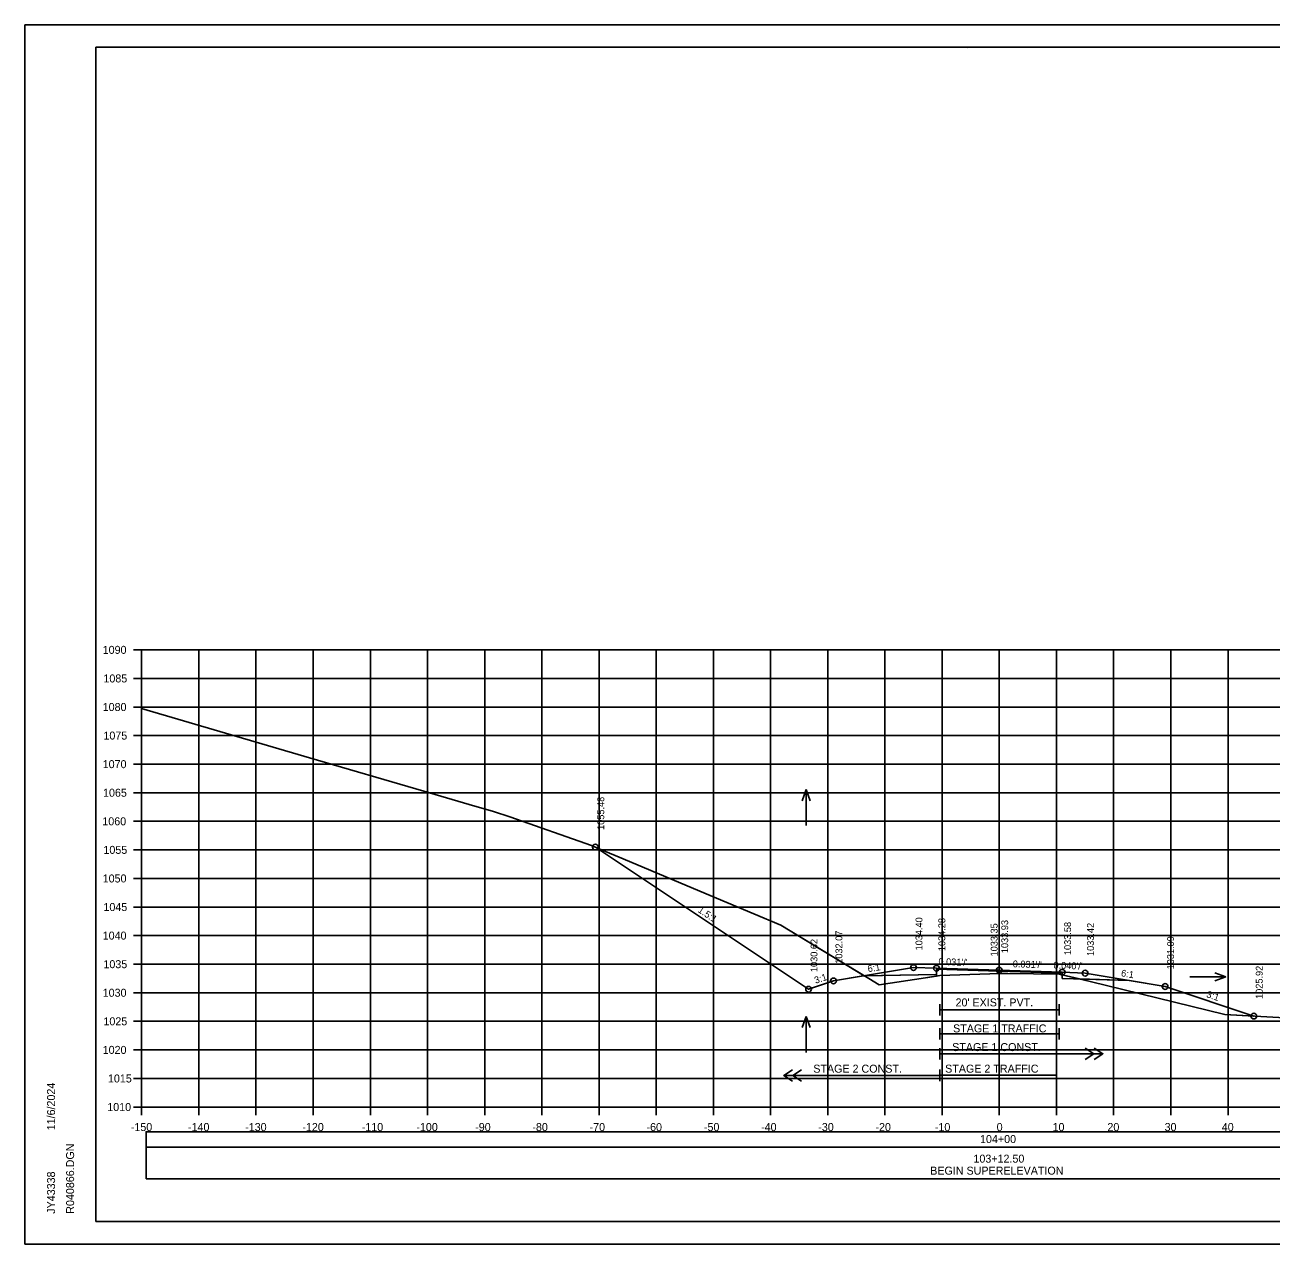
# Model space of a CAD drawing. Extents: x 1370565 to 1374448, y 301010 to 304637.
# Drawn here: x 1370564.6 to 1370782.6, y 301437.2 to 301650.5 of the extents above; entities that cross this region are included whole.
import ezdxf

# ---------------------------------------------------------------- set-up
doc = ezdxf.new("R2010")
doc.units = 0
for name, color, linetype in [('R_Alt Surface', 7, 'Continuous'), ('R_Axis', 7, 'Continuous'), ('R_Axis Annot', 7, 'Continuous'), ('R_Border', 7, 'Continuous'), ('R_Contours', 7, 'Continuous'), ('R_Drive', 7, 'Continuous'), ('R_Exist Surface', 7, 'Continuous'), ('R_Fin Surface', 7, 'Continuous'), ('R_Grid', 7, 'Continuous'), ('R_No Plot', 7, 'Continuous'), ('R_Water', 7, 'Continuous'), ('R_Water Annot', 7, 'Continuous'), ('R_Xsect Elev', 7, 'Continuous'), ('R_Xsect Slope', 7, 'Continuous')]:
    doc.layers.add(name, color=color, linetype=linetype)

msp = doc.modelspace()

# ---------------------------------------------------------------- linework, layer by layer
at = {"layer": 'R_Alt Surface'}
for points in [[(1370711.24, 301484.09), (1370724.03, 301484.35), (1370724.02, 301484.35), (1370724.03, 301485.26), (1370735.03, 301484.92), (1370746.03, 301484.57), (1370746.04, 301483.65), (1370746.03, 301483.65), (1370757.79, 301483.28)], [(1370724.65, 301479.15), (1370724.65, 301477.15)], [(1370745.49, 301479.15), (1370745.49, 301477.15)], [(1370724.65, 301478.15), (1370745.49, 301478.15)], [(1370724.65, 301474.94), (1370724.65, 301472.94)], [(1370745.49, 301474.94), (1370745.49, 301472.94)], [(1370724.65, 301473.94), (1370745.49, 301473.94)], [(1370724.65, 301471.47), (1370724.65, 301469.47)], [(1370724.65, 301470.47), (1370753.14, 301470.47)], [(1370750.04, 301471.47), (1370751.54, 301470.47), (1370750.04, 301469.47)], [(1370751.64, 301471.47), (1370753.14, 301470.47), (1370751.64, 301469.47)], [(1370698.84, 301467.68), (1370697.34, 301466.68), (1370698.84, 301465.68)], [(1370697.34, 301466.68), (1370724.65, 301466.68)], [(1370700.44, 301467.68), (1370698.94, 301466.68), (1370700.44, 301465.68)], [(1370724.65, 301467.7), (1370724.65, 301465.7)], [(1370724.65, 301466.7), (1370745.03, 301466.7)], [(1370745.03, 301467.7), (1370745.03, 301465.7)]]:
    msp.add_lwpolyline(points, dxfattribs=at)
at = {"layer": 'R_Axis'}
for p, q in [((1370583.63, 301541.15), (1370585.03, 301541.15)), ((1370585.03, 301461.15), (1370585.03, 301541.15)), ((1370583.63, 301536.15), (1370585.03, 301536.15)), ((1370583.63, 301531.15), (1370585.03, 301531.15)), ((1370583.63, 301526.15), (1370585.03, 301526.15)), ((1370583.63, 301521.15), (1370585.03, 301521.15)), ((1370583.63, 301516.15), (1370585.03, 301516.15)), ((1370583.63, 301511.15), (1370585.03, 301511.15)), ((1370583.63, 301506.15), (1370585.03, 301506.15)), ((1370583.63, 301501.15), (1370585.03, 301501.15)), ((1370583.63, 301496.15), (1370585.03, 301496.15)), ((1370583.63, 301491.15), (1370585.03, 301491.15)), ((1370583.63, 301486.15), (1370585.03, 301486.15)), ((1370583.63, 301481.15), (1370585.03, 301481.15)), ((1370583.63, 301476.15), (1370585.03, 301476.15)), ((1370583.63, 301471.15), (1370585.03, 301471.15)), ((1370583.63, 301466.15), (1370585.03, 301466.15)), ((1370583.63, 301461.15), (1370585.03, 301461.15)), ((1370585.03, 301461.15), (1370885.03, 301461.15)), ((1370585.03, 301459.75), (1370585.03, 301461.15)), ((1370595.03, 301459.75), (1370595.03, 301461.15)), ((1370605.03, 301459.75), (1370605.03, 301461.15)), ((1370615.03, 301459.75), (1370615.03, 301461.15)), ((1370625.03, 301459.75), (1370625.03, 301461.15)), ((1370635.03, 301459.75), (1370635.03, 301461.15)), ((1370645.03, 301459.75), (1370645.03, 301461.15)), ((1370655.03, 301459.75), (1370655.03, 301461.15)), ((1370665.03, 301459.75), (1370665.03, 301461.15)), ((1370675.03, 301459.75), (1370675.03, 301461.15)), ((1370685.03, 301459.75), (1370685.03, 301461.15)), ((1370695.03, 301459.75), (1370695.03, 301461.15)), ((1370705.03, 301459.75), (1370705.03, 301461.15)), ((1370715.03, 301459.75), (1370715.03, 301461.15)), ((1370725.03, 301459.75), (1370725.03, 301461.15)), ((1370735.03, 301459.75), (1370735.03, 301461.15)), ((1370745.03, 301459.75), (1370745.03, 301461.15)), ((1370755.03, 301459.75), (1370755.03, 301461.15)), ((1370765.03, 301459.75), (1370765.03, 301461.15)), ((1370775.03, 301459.75), (1370775.03, 301461.15))]:
    msp.add_line(p, q, dxfattribs=at)
for points in [[(1370724.65, 301479.15), (1370724.65, 301477.15)], [(1370745.49, 301479.15), (1370745.49, 301477.15)], [(1370724.65, 301478.15), (1370745.49, 301478.15)], [(1370724.65, 301474.94), (1370724.65, 301472.94)], [(1370745.49, 301474.94), (1370745.49, 301472.94)], [(1370724.65, 301473.94), (1370745.49, 301473.94)]]:
    msp.add_lwpolyline(points, dxfattribs=at)
at = {"layer": 'R_Border'}
for p, q in [((1370577.03, 301646.61), (1370893.21, 301646.61)), ((1370577.03, 301441.15), (1370577.03, 301646.61)), ((1370729.55, 301646.35), (1370729.55, 301646.35)), ((1370729.55, 301646.35), (1370729.55, 301646.35)), ((1370577.03, 301441.15), (1370577.03, 301441.15)), ((1370893.21, 301441.15), (1370577.03, 301441.15))]:
    msp.add_line(p, q, dxfattribs=at)
at = {"layer": 'R_Contours'}
for p, q in [((1370724.03, 301484.35), (1370711.47, 301484.09)), ((1370711.47, 301484.09), (1370712.23, 301483.63)), ((1370724.03, 301484.35), (1370724.03, 301484.05)), ((1370724.03, 301484.05), (1370724.03, 301484.35)), ((1370724.03, 301484.35), (1370724.03, 301484.05)), ((1370734.95, 301484.92), (1370734.95, 301484.5)), ((1370749.06, 301483.56), (1370746.03, 301484.29)), ((1370746.03, 301484.29), (1370746.04, 301483.65)), ((1370746.04, 301483.65), (1370749.06, 301483.56)), ((1370757.79, 301483.28), (1370749.06, 301483.56)), ((1370749.06, 301483.56), (1370750.95, 301483.1))]:
    msp.add_line(p, q, dxfattribs=at)
for points in [[(1370711.42, 301484.12), (1370696.82, 301492.95), (1370682.65, 301498.92), (1370669.22, 301504.57), (1370665.48, 301506.17), (1370664.38, 301506.64)], [(1370664.38, 301506.64), (1370701.67, 301481.77), (1370706.03, 301483.22), (1370711.24, 301484.09), (1370711.42, 301484.12)], [(1370712.23, 301483.63), (1370714.02, 301482.53), (1370722.1, 301483.75), (1370724.03, 301484.05)], [(1370734.95, 301484.92), (1370724.03, 301485.26), (1370724.03, 301484.35)], [(1370724.03, 301484.05), (1370724.65, 301484.15), (1370733.39, 301484.44), (1370734.95, 301484.5)], [(1370734.95, 301484.5), (1370734.95, 301484.92), (1370734.95, 301484.92)], [(1370735.03, 301484.92), (1370734.95, 301484.92)], [(1370734.95, 301484.5), (1370736.52, 301484.49), (1370745.49, 301484.42), (1370746.03, 301484.29)], [(1370746.03, 301484.29), (1370746.03, 301484.57), (1370735.03, 301484.92)], [(1370750.95, 301483.1), (1370774.5, 301477.35), (1370779.54, 301477.07)], [(1370779.54, 301477.07), (1370764.03, 301482.24), (1370757.79, 301483.28)]]:
    msp.add_lwpolyline(points, dxfattribs=at)
at = {"layer": 'R_Drive'}
for points in [[(1370585.82, 301454.14), (1370884.24, 301454.14), (1370884.24, 301456.84), (1370585.82, 301456.84)], [(1370585.82, 301448.61), (1370884.24, 301448.61), (1370884.24, 301454.14), (1370585.82, 301454.14)]]:
    msp.add_lwpolyline(points, close=True, dxfattribs=at)
at = {"layer": 'R_Exist Surface'}
msp.add_lwpolyline([(1370585.03, 301530.88), (1370614.38, 301522.28), (1370634.38, 301516.42), (1370642.31, 301514.1), (1370646.57, 301512.85), (1370649.44, 301511.92), (1370663.72, 301506.91), (1370665.48, 301506.17), (1370669.22, 301504.57), (1370682.65, 301498.92), (1370696.82, 301492.95), (1370712.23, 301483.63), (1370714.02, 301482.53), (1370722.1, 301483.75), (1370724.65, 301484.15), (1370733.39, 301484.44), (1370734.95, 301484.5), (1370736.52, 301484.49), (1370745.49, 301484.42), (1370750.95, 301483.1), (1370774.5, 301477.35), (1370814.43, 301475.14)], dxfattribs=at)
at = {"layer": 'R_Fin Surface'}
msp.add_lwpolyline([(1370664.38, 301506.64), (1370701.67, 301481.77), (1370706.03, 301483.22), (1370720.03, 301485.55), (1370724.03, 301485.43), (1370735.03, 301485.08), (1370746.03, 301484.74), (1370750.03, 301484.58), (1370764.03, 301482.24), (1370779.54, 301477.07)], dxfattribs=at)
at = {"layer": 'R_Grid'}
for p, q in [((1370585.03, 301541.15), (1370885.03, 301541.15)), ((1370585.03, 301461.15), (1370585.03, 301541.15)), ((1370595.03, 301461.15), (1370595.03, 301541.15)), ((1370605.03, 301461.15), (1370605.03, 301541.15)), ((1370615.03, 301461.15), (1370615.03, 301541.15)), ((1370625.03, 301461.15), (1370625.03, 301541.15)), ((1370635.03, 301461.15), (1370635.03, 301541.15)), ((1370645.03, 301461.15), (1370645.03, 301541.15)), ((1370655.03, 301461.15), (1370655.03, 301541.15)), ((1370665.03, 301461.15), (1370665.03, 301541.15)), ((1370675.03, 301461.15), (1370675.03, 301541.15)), ((1370685.03, 301461.15), (1370685.03, 301541.15)), ((1370695.03, 301461.15), (1370695.03, 301541.15)), ((1370705.03, 301461.15), (1370705.03, 301541.15)), ((1370715.03, 301461.15), (1370715.03, 301541.15)), ((1370725.03, 301461.15), (1370725.03, 301541.15)), ((1370735.03, 301461.15), (1370735.03, 301541.15)), ((1370745.03, 301461.15), (1370745.03, 301541.15)), ((1370755.03, 301461.15), (1370755.03, 301541.15)), ((1370765.03, 301461.15), (1370765.03, 301541.15)), ((1370775.03, 301461.15), (1370775.03, 301541.15)), ((1370585.03, 301536.15), (1370885.03, 301536.15)), ((1370585.03, 301531.15), (1370885.03, 301531.15)), ((1370585.03, 301526.15), (1370885.03, 301526.15)), ((1370585.03, 301521.15), (1370885.03, 301521.15)), ((1370585.03, 301516.15), (1370885.03, 301516.15)), ((1370585.03, 301511.15), (1370885.03, 301511.15)), ((1370585.03, 301506.15), (1370885.03, 301506.15)), ((1370585.03, 301501.15), (1370885.03, 301501.15)), ((1370585.03, 301496.15), (1370885.03, 301496.15)), ((1370585.03, 301491.15), (1370885.03, 301491.15)), ((1370585.03, 301486.15), (1370885.03, 301486.15)), ((1370585.03, 301481.15), (1370885.03, 301481.15)), ((1370585.03, 301476.15), (1370885.03, 301476.15)), ((1370585.03, 301471.15), (1370885.03, 301471.15)), ((1370585.03, 301466.15), (1370885.03, 301466.15)), ((1370585.03, 301461.15), (1370885.03, 301461.15))]:
    msp.add_line(p, q, dxfattribs=at)
at = {"layer": 'R_No Plot'}
for p, q in [((1370564.63, 301650.51), (1370897.96, 301650.51)), ((1370564.63, 301437.17), (1370897.96, 301437.17))]:
    msp.add_line(p, q, dxfattribs=at)
for points in [[(1370564.62, 301650.51), (1370897.96, 301650.51), (1370897.96, 301437.17), (1370564.62, 301437.17)], [(1370810.95, 301646.61), (1370830.57, 301646.61), (1370830.57, 301636.73), (1370846.68, 301636.73), (1370869.88, 301636.73), (1370869.88, 301604.06), (1370893.09, 301604.06), (1370893.21, 301441.15), (1370577.03, 301441.15), (1370577.03, 301646.61)]]:
    msp.add_lwpolyline(points, close=True, dxfattribs=at)
for centre in [(1370664.38, 301506.64), (1370720.03, 301485.55), (1370724.03, 301485.43), (1370735.03, 301485.08), (1370706.03, 301483.22), (1370746.03, 301484.74), (1370750.03, 301484.58), (1370701.67, 301481.77), (1370764.03, 301482.24), (1370779.54, 301477.07)]:
    msp.add_circle(centre, 0.5, dxfattribs=at)
at = {"layer": 'R_Water Annot'}
for p, q in [((1370701.24, 301516.69), (1370700.54, 301514.76)), ((1370701.24, 301510.4), (1370701.24, 301516.69)), ((1370701.24, 301516.69), (1370701.94, 301514.76)), ((1370768.36, 301483.92), (1370774.64, 301483.92)), ((1370774.64, 301483.92), (1370772.72, 301484.62)), ((1370774.64, 301483.92), (1370772.72, 301483.22)), ((1370701.24, 301477), (1370700.54, 301475.07)), ((1370701.24, 301470.71), (1370701.24, 301477)), ((1370701.24, 301477), (1370701.94, 301475.07))]:
    msp.add_line(p, q, dxfattribs=at)
at = {"layer": 'R_Xsect Elev'}
msp.add_line((1370735.03, 301484.5), (1370735.03, 301494.5), dxfattribs=at)

# ---------------------------------------------------------------- texts
at = {"layer": 'R_Axis Annot'}
for s, p in [('1090', (1370578.22, 301540.45)), ('1085', (1370578.35, 301535.45)), ('1080', (1370578.22, 301530.45)), ('1075', (1370578.35, 301525.45)), ('1070', (1370578.22, 301520.45)), ('1065', (1370578.28, 301515.45)), ('1060', (1370578.16, 301510.45)), ('1055', (1370578.35, 301505.45)), ('1050', (1370578.22, 301500.45)), ('1045', (1370578.35, 301495.45)), ('1040', (1370578.22, 301490.45)), ('1035', (1370578.35, 301485.45)), ('1030', (1370578.22, 301480.45)), ("20' EXIST. PVT.", (1370727.38, 301478.76)), ('1025', (1370578.35, 301475.45)), ('1020', (1370578.22, 301470.45)), ('1015', (1370579.14, 301465.45)), ('1010', (1370579.02, 301460.45)), ('-150', (1370583.14, 301456.95)), ('-140', (1370593.14, 301456.95)), ('-130', (1370603.14, 301456.95)), ('-120', (1370613.14, 301456.95)), ('-110', (1370623.53, 301456.95)), ('-100', (1370633.08, 301456.95)), ('-90', (1370643.37, 301456.95)), ('-80', (1370653.37, 301456.95)), ('-70', (1370663.37, 301456.95)), ('-60', (1370673.33, 301456.95)), ('-50', (1370683.37, 301456.95)), ('-40', (1370693.37, 301456.95)), ('-30', (1370703.37, 301456.95)), ('-20', (1370713.37, 301456.95)), ('-10', (1370723.76, 301456.95)), ('0', (1370734.57, 301456.95)), ('10', (1370744.34, 301456.95)), ('20', (1370753.94, 301456.95)), ('30', (1370763.94, 301456.95)), ('40', (1370773.94, 301456.95)), ('104+00', (1370731.66, 301454.85)), ('BEGIN SUPERELEVATION', (1370722.95, 301449.32)), ('103+12.50', (1370730.51, 301451.42))]:
    msp.add_text(s, height=1.4, dxfattribs=at).set_placement(p)
at = {"layer": 'R_Border'}
for s, p in [('11/6/2024', (1370569.89, 301457.08)), ('R040866.DGN', (1370573.22, 301442.48)), ('JY43338', (1370569.89, 301442.48))]:
    msp.add_text(s, height=1.4, rotation=90, dxfattribs=at).set_placement(p)
at = {"layer": 'R_Water'}
for s, p in [('STAGE 1 TRAFFIC', (1370726.95, 301474.21)), ('STAGE 1 CONST.', (1370726.79, 301470.94)), ('STAGE 2 CONST.', (1370702.5, 301467.16)), ('STAGE 2 TRAFFIC', (1370725.56, 301467.17))]:
    msp.add_text(s, height=1.4, dxfattribs=at).set_placement(p)
at = {"layer": 'R_Xsect Elev'}
for s, p in [('1055.48', (1370665.93, 301509.64)), ('1034.40', (1370721.58, 301488.55)), ('1034.28', (1370725.58, 301488.43)), ('1033.35', (1370734.73, 301487.5)), ('1033.93', (1370736.58, 301488.08)), ('1033.58', (1370747.58, 301487.74)), ('1033.42', (1370751.58, 301487.58)), ('1030.62', (1370703.22, 301484.77)), ('1032.07', (1370707.58, 301486.22)), ('1031.09', (1370765.58, 301485.24)), ('1025.92', (1370781.09, 301480.07))]:
    msp.add_text(s, height=1.2, rotation=90, dxfattribs=at).set_placement(p)
at = {"layer": 'R_Xsect Slope'}
for s, rotation, p in [('1.5:1', 326.3086, (1370682.2, 301495.35)), ('6:1', 9.4642, (1370712.1, 301484.74)), ("0.031'/'", 358.1959, (1370724.37, 301486.02)), ("0.031'/'", 358.1959, (1370737.37, 301485.61)), ("0.040'/'", 357.7094, (1370744.49, 301485.4)), ('3:1', 18.4349, (1370702.9, 301482.71)), ('6:1', 350.5358, (1370756.26, 301484.04)), ('3:1', 341.5651, (1370771.15, 301480.39))]:
    msp.add_text(s, height=1.2, rotation=rotation, dxfattribs=at).set_placement(p)

doc.saveas('drawing.dxf')
